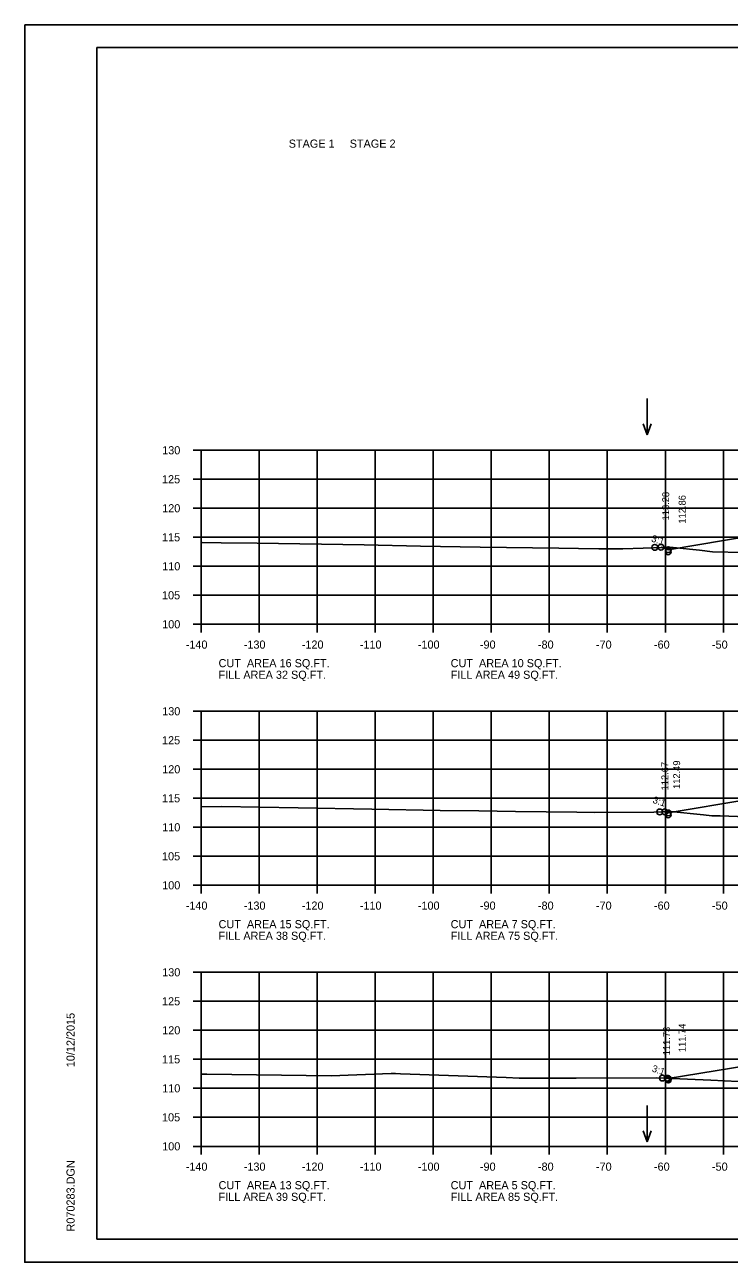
# Model space of a CAD drawing. Extents: x 1175611 to 1176402, y -433344 to -416213.
# Drawn here: x 1175610.6 to 1175732, y -421609.9 to -421396.6 of the extents above; entities that cross this region are included whole.
import ezdxf

# ---------------------------------------------------------------- set-up
doc = ezdxf.new("R2010")
doc.units = 0
for name, color, linetype in [('Default', 7, 'Continuous'), ('R_Axis', 7, 'Continuous'), ('R_Axis Annot', 7, 'Continuous'), ('R_Border', 7, 'Continuous'), ('R_Exist Surface', 7, 'Continuous'), ('R_Fin Surface', 7, 'Continuous'), ('R_Grid', 7, 'Continuous'), ('R_No Plot', 7, 'Continuous'), ('R_Water Annot', 7, 'Continuous'), ('R_Xsect Elev', 7, 'Continuous'), ('R_Xsect Slope', 7, 'Continuous')]:
    doc.layers.add(name, color=color, linetype=linetype)

msp = doc.modelspace()

# ---------------------------------------------------------------- linework, layer by layer
at = {"layer": 'R_Axis'}
for p, q in [((1175639.57, -421469.96), (1175640.97, -421469.96)), ((1175640.97, -421499.96), (1175640.97, -421469.96)), ((1175639.57, -421474.96), (1175640.97, -421474.96)), ((1175639.57, -421479.96), (1175640.97, -421479.96)), ((1175639.57, -421484.96), (1175640.97, -421484.96)), ((1175639.57, -421489.96), (1175640.97, -421489.96)), ((1175639.57, -421494.96), (1175640.97, -421494.96)), ((1175639.57, -421499.96), (1175640.97, -421499.96)), ((1175640.97, -421499.96), (1175920.97, -421499.96)), ((1175640.97, -421501.36), (1175640.97, -421499.96)), ((1175650.97, -421501.36), (1175650.97, -421499.96)), ((1175660.97, -421501.36), (1175660.97, -421499.96)), ((1175670.97, -421501.36), (1175670.97, -421499.96)), ((1175680.97, -421501.36), (1175680.97, -421499.96)), ((1175690.97, -421501.36), (1175690.97, -421499.96)), ((1175700.97, -421501.36), (1175700.97, -421499.96)), ((1175710.97, -421501.36), (1175710.97, -421499.96)), ((1175720.97, -421501.36), (1175720.97, -421499.96)), ((1175730.97, -421501.36), (1175730.97, -421499.96)), ((1175639.57, -421514.96), (1175640.97, -421514.96)), ((1175640.97, -421544.96), (1175640.97, -421514.96)), ((1175639.57, -421519.96), (1175640.97, -421519.96)), ((1175639.57, -421524.96), (1175640.97, -421524.96)), ((1175639.57, -421529.96), (1175640.97, -421529.96)), ((1175639.57, -421534.96), (1175640.97, -421534.96)), ((1175639.57, -421539.96), (1175640.97, -421539.96)), ((1175639.57, -421544.96), (1175640.97, -421544.96)), ((1175640.97, -421544.96), (1175920.97, -421544.96)), ((1175640.97, -421546.36), (1175640.97, -421544.96)), ((1175650.97, -421546.36), (1175650.97, -421544.96)), ((1175660.97, -421546.36), (1175660.97, -421544.96)), ((1175670.97, -421546.36), (1175670.97, -421544.96)), ((1175680.97, -421546.36), (1175680.97, -421544.96)), ((1175690.97, -421546.36), (1175690.97, -421544.96)), ((1175700.97, -421546.36), (1175700.97, -421544.96)), ((1175710.97, -421546.36), (1175710.97, -421544.96)), ((1175720.97, -421546.36), (1175720.97, -421544.96)), ((1175730.97, -421546.36), (1175730.97, -421544.96)), ((1175639.57, -421559.96), (1175640.97, -421559.96)), ((1175640.97, -421589.96), (1175640.97, -421559.96)), ((1175639.57, -421564.96), (1175640.97, -421564.96)), ((1175639.57, -421569.96), (1175640.97, -421569.96)), ((1175639.57, -421574.96), (1175640.97, -421574.96)), ((1175639.57, -421579.96), (1175640.97, -421579.96)), ((1175639.57, -421584.96), (1175640.97, -421584.96)), ((1175639.57, -421589.96), (1175640.97, -421589.96)), ((1175640.97, -421589.96), (1175920.97, -421589.96)), ((1175640.97, -421591.36), (1175640.97, -421589.96)), ((1175650.97, -421591.36), (1175650.97, -421589.96)), ((1175660.97, -421591.36), (1175660.97, -421589.96)), ((1175670.97, -421591.36), (1175670.97, -421589.96)), ((1175680.97, -421591.36), (1175680.97, -421589.96)), ((1175690.97, -421591.36), (1175690.97, -421589.96)), ((1175700.97, -421591.36), (1175700.97, -421589.96)), ((1175710.97, -421591.36), (1175710.97, -421589.96)), ((1175720.97, -421591.36), (1175720.97, -421589.96)), ((1175730.97, -421591.36), (1175730.97, -421589.96))]:
    msp.add_line(p, q, dxfattribs=at)
at = {"layer": 'R_Border'}
for p, q in [((1175622.97, -421400.5), (1175939.15, -421400.5)), ((1175622.97, -421605.96), (1175622.97, -421400.5)), ((1175622.97, -421605.96), (1175622.97, -421605.96)), ((1175939.15, -421605.96), (1175622.97, -421605.96))]:
    msp.add_line(p, q, dxfattribs=at)
at = {"layer": 'R_Exist Surface'}
for points in [[(1175641.12, -421485.86), (1175644.44, -421485.92), (1175650.63, -421485.99), (1175669.05, -421486.28), (1175678.78, -421486.49), (1175689.07, -421486.68), (1175702.63, -421486.85), (1175706.03, -421486.89), (1175709.48, -421486.93), (1175713.64, -421486.95), (1175720.64, -421486.75), (1175722.07, -421486.7), (1175722.32, -421486.73), (1175726.86, -421487.21), (1175729.12, -421487.45), (1175734.43, -421487.59)], [(1175640.97, -421531.44), (1175644.45, -421531.37), (1175657.7, -421531.59), (1175670.36, -421531.84), (1175682.16, -421532.04), (1175688.83, -421532.13), (1175695.17, -421532.23), (1175705.74, -421532.38), (1175708.69, -421532.41), (1175718.98, -421532.35), (1175721.84, -421532.26), (1175727.52, -421532.82), (1175728.99, -421532.97), (1175730.4, -421533.01), (1175734.91, -421533.13)], [(1175640.97, -421577.51), (1175641.92, -421577.52), (1175663.38, -421577.78), (1175673.69, -421577.43), (1175673.98, -421577.42), (1175674.45, -421577.43), (1175675.31, -421577.46), (1175693.55, -421578.11), (1175695.79, -421578.23), (1175705.59, -421578.2), (1175719.44, -421578.14), (1175728.83, -421578.57), (1175735.86, -421578.87)]]:
    msp.add_lwpolyline(points, dxfattribs=at)
at = {"layer": 'R_Fin Surface'}
for points in [[(1175720.22, -421486.68), (1175721.31, -421487.04), (1175721.47, -421487.1), (1175731.36, -421485.45), (1175735.2, -421484.81)], [(1175720.9, -421532.29), (1175721.47, -421532.48), (1175735.2, -421530.19), (1175743.47, -421528.81), (1175749.47, -421528.57), (1175751.47, -421528.53), (1175780.97, -421527.94), (1175810.47, -421528.53), (1175812.47, -421528.57), (1175818.47, -421528.81), (1175826.75, -421530.19), (1175840.47, -421532.48), (1175842.55, -421533.17), (1175844.22, -421532.61)], [(1175721.28, -421578.22), (1175721.47, -421578.29), (1175735.2, -421576), (1175743.47, -421574.62), (1175749.47, -421574.38), (1175751.47, -421574.34), (1175780.97, -421573.75), (1175810.47, -421574.34), (1175812.47, -421574.38), (1175818.47, -421574.62), (1175826.75, -421576), (1175840.47, -421578.29), (1175841.63, -421578.68)]]:
    msp.add_lwpolyline(points, dxfattribs=at)
at = {"layer": 'R_Grid'}
for p, q in [((1175640.97, -421469.96), (1175920.97, -421469.96)), ((1175640.97, -421499.96), (1175640.97, -421469.96)), ((1175640.97, -421469.96), (1175920.97, -421469.96)), ((1175640.97, -421499.96), (1175640.97, -421469.96)), ((1175650.97, -421499.96), (1175650.97, -421469.96)), ((1175650.97, -421499.96), (1175650.97, -421469.96)), ((1175660.97, -421499.96), (1175660.97, -421469.96)), ((1175660.97, -421499.96), (1175660.97, -421469.96)), ((1175670.97, -421499.96), (1175670.97, -421469.96)), ((1175670.97, -421499.96), (1175670.97, -421469.96)), ((1175680.97, -421499.96), (1175680.97, -421469.96)), ((1175680.97, -421499.96), (1175680.97, -421469.96)), ((1175690.97, -421499.96), (1175690.97, -421469.96)), ((1175690.97, -421499.96), (1175690.97, -421469.96)), ((1175700.97, -421499.96), (1175700.97, -421469.96)), ((1175700.97, -421499.96), (1175700.97, -421469.96)), ((1175710.97, -421499.96), (1175710.97, -421469.96)), ((1175710.97, -421499.96), (1175710.97, -421469.96)), ((1175720.97, -421499.96), (1175720.97, -421469.96)), ((1175720.97, -421499.96), (1175720.97, -421469.96)), ((1175730.97, -421499.96), (1175730.97, -421469.96)), ((1175730.97, -421499.96), (1175730.97, -421469.96)), ((1175640.97, -421474.96), (1175920.97, -421474.96)), ((1175640.97, -421474.96), (1175920.97, -421474.96)), ((1175640.97, -421479.96), (1175920.97, -421479.96)), ((1175640.97, -421479.96), (1175920.97, -421479.96)), ((1175640.97, -421484.96), (1175920.97, -421484.96)), ((1175640.97, -421484.96), (1175920.97, -421484.96)), ((1175640.97, -421489.96), (1175920.97, -421489.96)), ((1175640.97, -421489.96), (1175920.97, -421489.96)), ((1175640.97, -421494.96), (1175920.97, -421494.96)), ((1175640.97, -421494.96), (1175920.97, -421494.96)), ((1175640.97, -421499.96), (1175920.97, -421499.96)), ((1175640.97, -421499.96), (1175920.97, -421499.96)), ((1175640.97, -421514.96), (1175920.97, -421514.96)), ((1175640.97, -421544.96), (1175640.97, -421514.96)), ((1175650.97, -421544.96), (1175650.97, -421514.96)), ((1175660.97, -421544.96), (1175660.97, -421514.96)), ((1175670.97, -421544.96), (1175670.97, -421514.96)), ((1175680.97, -421544.96), (1175680.97, -421514.96)), ((1175690.97, -421544.96), (1175690.97, -421514.96)), ((1175700.97, -421544.96), (1175700.97, -421514.96)), ((1175710.97, -421544.96), (1175710.97, -421514.96)), ((1175720.97, -421544.96), (1175720.97, -421514.96)), ((1175730.97, -421544.96), (1175730.97, -421514.96)), ((1175640.97, -421519.96), (1175920.97, -421519.96)), ((1175640.97, -421524.96), (1175920.97, -421524.96)), ((1175640.97, -421529.96), (1175920.97, -421529.96)), ((1175640.97, -421534.96), (1175920.97, -421534.96)), ((1175640.97, -421539.96), (1175920.97, -421539.96)), ((1175640.97, -421544.96), (1175920.97, -421544.96)), ((1175640.97, -421559.96), (1175920.97, -421559.96)), ((1175640.97, -421589.96), (1175640.97, -421559.96)), ((1175650.97, -421589.96), (1175650.97, -421559.96)), ((1175660.97, -421589.96), (1175660.97, -421559.96)), ((1175670.97, -421589.96), (1175670.97, -421559.96)), ((1175680.97, -421589.96), (1175680.97, -421559.96)), ((1175690.97, -421589.96), (1175690.97, -421559.96)), ((1175700.97, -421589.96), (1175700.97, -421559.96)), ((1175710.97, -421589.96), (1175710.97, -421559.96)), ((1175720.97, -421589.96), (1175720.97, -421559.96)), ((1175730.97, -421589.96), (1175730.97, -421559.96)), ((1175640.97, -421564.96), (1175920.97, -421564.96)), ((1175640.97, -421569.96), (1175920.97, -421569.96)), ((1175640.97, -421574.96), (1175920.97, -421574.96)), ((1175640.97, -421579.96), (1175920.97, -421579.96)), ((1175640.97, -421584.96), (1175920.97, -421584.96)), ((1175640.97, -421589.96), (1175920.97, -421589.96))]:
    msp.add_line(p, q, dxfattribs=at)
at = {"layer": 'R_No Plot'}
for p, q in [((1175610.57, -421396.61), (1175943.91, -421396.61)), ((1175610.57, -421609.94), (1175943.91, -421609.94))]:
    msp.add_line(p, q, dxfattribs=at)
msp.add_lwpolyline([(1175610.57, -421396.61), (1175943.91, -421396.61), (1175943.91, -421609.94), (1175610.57, -421609.94)], close=True, dxfattribs=at)
for centre in [(1175719.15, -421486.7), (1175720.22, -421486.68), (1175720.22, -421486.68), (1175721.47, -421487.1), (1175721.47, -421487.47), (1175720, -421532.32), (1175720.9, -421532.29), (1175720.9, -421532.29), (1175721.47, -421532.48), (1175721.47, -421532.81), (1175720.46, -421578.19), (1175721.28, -421578.22), (1175721.28, -421578.22), (1175721.47, -421578.29), (1175721.47, -421578.52)]:
    msp.add_circle(centre, 0.5, dxfattribs=at)
at = {"layer": 'R_Water Annot'}
for p, q in [((1175717.84, -421461.03), (1175717.84, -421467.32)), ((1175717.84, -421467.32), (1175717.14, -421465.39)), ((1175717.84, -421467.32), (1175718.54, -421465.39)), ((1175717.84, -421582.93), (1175717.84, -421589.21)), ((1175717.84, -421589.21), (1175717.14, -421587.29)), ((1175717.84, -421589.21), (1175718.54, -421587.29))]:
    msp.add_line(p, q, dxfattribs=at)

# ---------------------------------------------------------------- texts
at = {"layer": 'Default'}
for s, p in [('STAGE 1     STAGE 2', (1175656.06, -421417.8)), ('CUT  AREA 16 SQ.FT.', (1175643.97, -421507.36)), ('CUT  AREA 10 SQ.FT.', (1175683.97, -421507.36)), ('FILL AREA 32 SQ.FT.', (1175643.97, -421509.36)), ('FILL AREA 49 SQ.FT.', (1175683.97, -421509.36)), ('CUT  AREA 15 SQ.FT.', (1175643.97, -421552.36)), ('FILL AREA 38 SQ.FT.', (1175643.97, -421554.36)), ('CUT  AREA 7 SQ.FT.', (1175683.97, -421552.36)), ('FILL AREA 75 SQ.FT.', (1175683.97, -421554.36)), ('CUT  AREA 13 SQ.FT.', (1175643.97, -421597.36)), ('CUT  AREA 5 SQ.FT.', (1175683.97, -421597.36)), ('FILL AREA 39 SQ.FT.', (1175643.97, -421599.36)), ('FILL AREA 85 SQ.FT.', (1175683.97, -421599.36))]:
    msp.add_text(s, height=1.4, dxfattribs=at).set_placement(p)
at = {"layer": 'R_Axis Annot'}
for s, p in [('130', (1175634.25, -421470.66)), ('125', (1175634.22, -421475.66)), ('120', (1175634.25, -421480.66)), ('115', (1175634.22, -421485.66)), ('110', (1175634.25, -421490.66)), ('105', (1175634.22, -421495.66)), ('100', (1175634.25, -421500.66)), ('-140', (1175638.31, -421504.16)), ('-130', (1175648.31, -421504.16)), ('-120', (1175658.31, -421504.16)), ('-110', (1175668.31, -421504.16)), ('-100', (1175678.31, -421504.16)), ('-90', (1175689.01, -421504.16)), ('-80', (1175699.01, -421504.16)), ('-70', (1175709.01, -421504.16)), ('-60', (1175719.01, -421504.16)), ('-50', (1175729.01, -421504.16)), ('130', (1175634.25, -421515.66)), ('125', (1175634.22, -421520.66)), ('120', (1175634.25, -421525.66)), ('115', (1175634.22, -421530.66)), ('110', (1175634.25, -421535.66)), ('105', (1175634.22, -421540.66)), ('100', (1175634.25, -421545.66)), ('-140', (1175638.31, -421549.16)), ('-130', (1175648.31, -421549.16)), ('-120', (1175658.31, -421549.16)), ('-110', (1175668.31, -421549.16)), ('-100', (1175678.31, -421549.16)), ('-90', (1175689.01, -421549.16)), ('-80', (1175699.01, -421549.16)), ('-70', (1175709.01, -421549.16)), ('-60', (1175719.01, -421549.16)), ('-50', (1175729.01, -421549.16)), ('130', (1175634.25, -421560.66)), ('125', (1175634.22, -421565.66)), ('120', (1175634.25, -421570.66)), ('115', (1175634.22, -421575.66)), ('110', (1175634.25, -421580.66)), ('105', (1175634.22, -421585.66)), ('100', (1175634.25, -421590.66)), ('-140', (1175638.31, -421594.16)), ('-130', (1175648.31, -421594.16)), ('-120', (1175658.31, -421594.16)), ('-110', (1175668.31, -421594.16)), ('-100', (1175678.31, -421594.16)), ('-90', (1175689.01, -421594.16)), ('-80', (1175699.01, -421594.16)), ('-70', (1175709.01, -421594.16)), ('-60', (1175719.01, -421594.16)), ('-50', (1175729.01, -421594.16))]:
    msp.add_text(s, height=1.4, dxfattribs=at).set_placement(p)
at = {"layer": 'R_Border'}
for s, p in [('10/12/2015', (1175619.16, -421576.32)), ('R070283.DGN', (1175619.16, -421604.64))]:
    msp.add_text(s, height=1.4, rotation=90, dxfattribs=at).set_placement(p)
at = {"layer": 'R_Xsect Elev'}
for s, p in [('113.28', (1175721.63, -421482.05)), ('112.86', (1175724.47, -421482.6)), ('112.67', (1175721.49, -421528.6)), ('112.49', (1175723.52, -421528.35)), ('111.73', (1175721.78, -421574.27)), ('111.74', (1175724.47, -421573.72))]:
    msp.add_text(s, height=1.2, rotation=90, dxfattribs=at).set_placement(p)
at = {"layer": 'R_Xsect Slope'}
for p in [(1175718.45, -421485.65), (1175718.7, -421530.71), (1175718.56, -421577.03)]:
    msp.add_text('3:1', height=1.2, rotation=341.5651, dxfattribs=at).set_placement(p)

doc.saveas('drawing.dxf')
